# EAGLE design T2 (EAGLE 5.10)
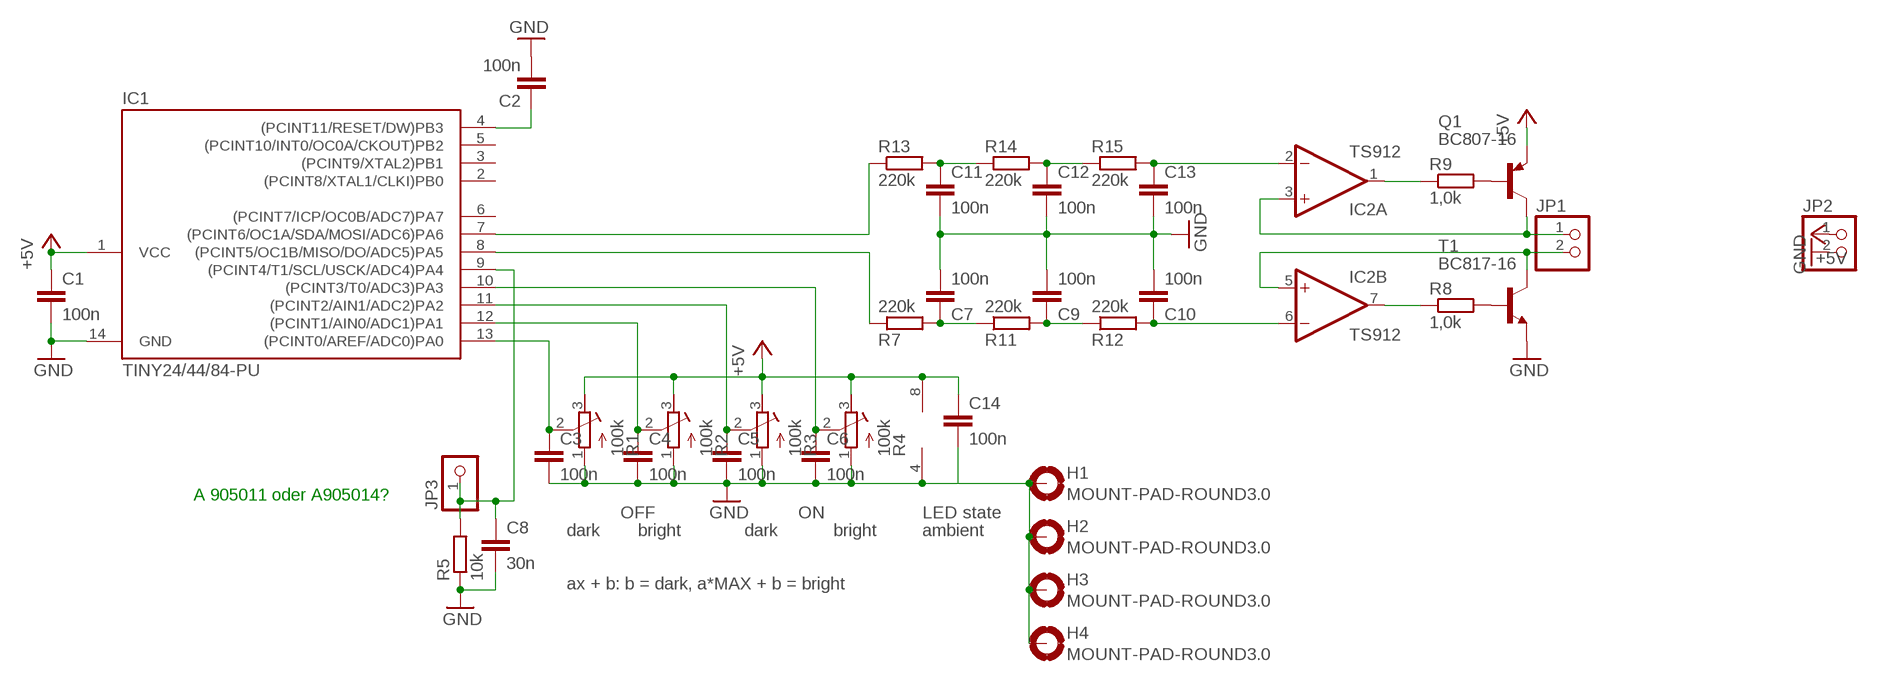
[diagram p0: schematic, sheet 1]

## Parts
C1  100n  C-EUC0805  [C0805]
C2  100n  C-EUC0805  [C0805]
C3  100n  C-EUC0805  [C0805]
C4  100n  C-EUC0805  [C0805]
C5  100n  C-EUC0805  [C0805]
C6  100n  C-EUC0805  [C0805]
C7  100n  C-EUC0805  [C0805]
C8  30n  C-EUC0805  [C0805]
C9  100n  C-EUC0805  [C0805]
C10  100n  C-EUC0805  [C0805]
C11  100n  C-EUC0805  [C0805]
C12  100n  C-EUC0805  [C0805]
C13  100n  C-EUC0805  [C0805]
C14  100n  C-EUC0805  [C0805]
H1  MOUNT-PAD-ROUND3.0  [3,0-PAD]
H2  MOUNT-PAD-ROUND3.0  [3,0-PAD]
H3  MOUNT-PAD-ROUND3.0  [3,0-PAD]
H4  MOUNT-PAD-ROUND3.0  [3,0-PAD]
IC1  TINY24/44/84-PU  [DIL14]
IC2  TS912  LM358N  [DIL08]
JP1  PINHD-1X2  [1X02]
JP2  PINHD-1X2  [1X02]
JP3  PINHD-1X1  [1X01]
Q1  BC807-16  BC807-16-PNP-SOT23-BEC  [SOT23-BEC]
R1  100k  R-TRIMM64W  [RTRIM64W]
R2  100k  R-TRIMM64W  [RTRIM64W]
R3  100k  R-TRIMM64W  [RTRIM64W]
R4  100k  R-TRIMM64W  [RTRIM64W]
R5  10k  R-EU_R0805  [R0805]
R7  220k  R-EU_R0805  [R0805]
R8  1,0k  R-EU_R0805  [R0805]
R9  1,0k  R-EU_R0805  [R0805]
R11  220k  R-EU_R0805  [R0805]
R12  220k  R-EU_R0805  [R0805]
R13  220k  R-EU_R0805  [R0805]
R14  220k  R-EU_R0805  [R0805]
R15  220k  R-EU_R0805  [R0805]
T1  BC817-16  BC817-16-NPN-SOT23-BEC  [SOT23-BEC]

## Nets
+5V: C1.1 C14.1 IC1.1(VCC) IC2.8(P:V+) JP2.1 Q1.E R1.3(A) R2.3(A) R3.3(A) R4.3(A)
GND: C1.2 C2.2 C3.2 C4.2 C5.2 C6.2 C7.2 C8.2 C9.2 C10.2 C11.2 C12.2 C13.2 C14.2 H1.B3,0(MOUNT) H2.B3,0(MOUNT) H3.B3,0(MOUNT) H4.B3,0(MOUNT) IC1.14(GND) IC2.4(P:V-) JP2.2 R1.1(E) R2.1(E) R3.1(E) R4.1(E) R5.1 T1.E
N$1: C2.1 IC1.4((PCINT11/RESET/DW)PB3)
N$3: IC2.7(B:OUT) R8.1
N$4: IC2.1(A:OUT) R9.1
N$5: IC1.8((PCINT5/OC1B/MISO/DO/ADC5)PA5) R7.1
N$6: IC1.7((PCINT6/OC1A/SDA/MOSI/ADC6)PA6) R13.1
N$7: C3.1 IC1.13((PCINT0/AREF/ADC0)PA0) R1.2(S)
N$8: C4.1 IC1.12((PCINT1/AIN0/ADC1)PA1) R2.2(S)
N$9: C5.1 IC1.11((PCINT2/AIN1/ADC2)PA2) R3.2(S)
N$10: C6.1 IC1.10((PCINT3/T0/ADC3)PA3) R4.2(S)
N$11: C8.1 IC1.9((PCINT4/T1/SCL/USCK/ADC4)PA4) JP3.1 R5.2
N$12: Q1.B R9.2
N$13: R8.2 T1.B
N$16: C7.1 R7.2 R11.1
N$17: C9.1 R11.2 R12.1
N$18: C10.1 IC2.6(B:-IN) R12.2
N$19: C11.1 R13.2 R14.1
N$20: C12.1 R14.2 R15.1
N$21: C13.1 IC2.2(A:-IN) R15.2
N$54: IC2.5(B:+IN) JP1.2 T1.C
N$55: IC2.3(A:+IN) JP1.1 Q1.C
Unconnected: IC1.2((PCINT8/XTAL1/CLKI)PB0) IC1.3((PCINT9/XTAL2)PB1) IC1.5((PCINT10/INT0/OC0A/CKOUT)PB2) IC1.6((PCINT7/ICP/OC0B/ADC7)PA7)

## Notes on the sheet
- A 905011 oder A905014?
- OFF | ON | LED state
- dark | bright | dark | bright | ambient
- ax + b: b = dark, a*MAX + b = bright

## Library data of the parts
C1-C14 = rcl:C-EU: CAPACITOR, European symbol
H1-H4 = holes:MOUNT-PAD-ROUND: MOUNTING PAD, round
IC1 = avr-6:TINY24/44/84
IC2 = linear:LM358: OP AMP also LM158; LM258; LM2904 Source: http://cache.national.com/ds/LM/LM158.pdf
JP1 JP2 = pinhead:PINHD-1X2: PIN HEADER
JP3 = pinhead:PINHD-1X1: PIN HEADER
Q1 = transistor:*-PNP-: PNP Transistror
R1-R4 = rcl:R-TRIMM: Trimm resistor
R5 R7-R9 R11-R15 = rcl:R-EU_: RESISTOR, European symbol
T1 = transistor:*-NPN-: NPN Transistror BF959 corrected 2008.03.06

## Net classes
1 Power: width 0.5 mm

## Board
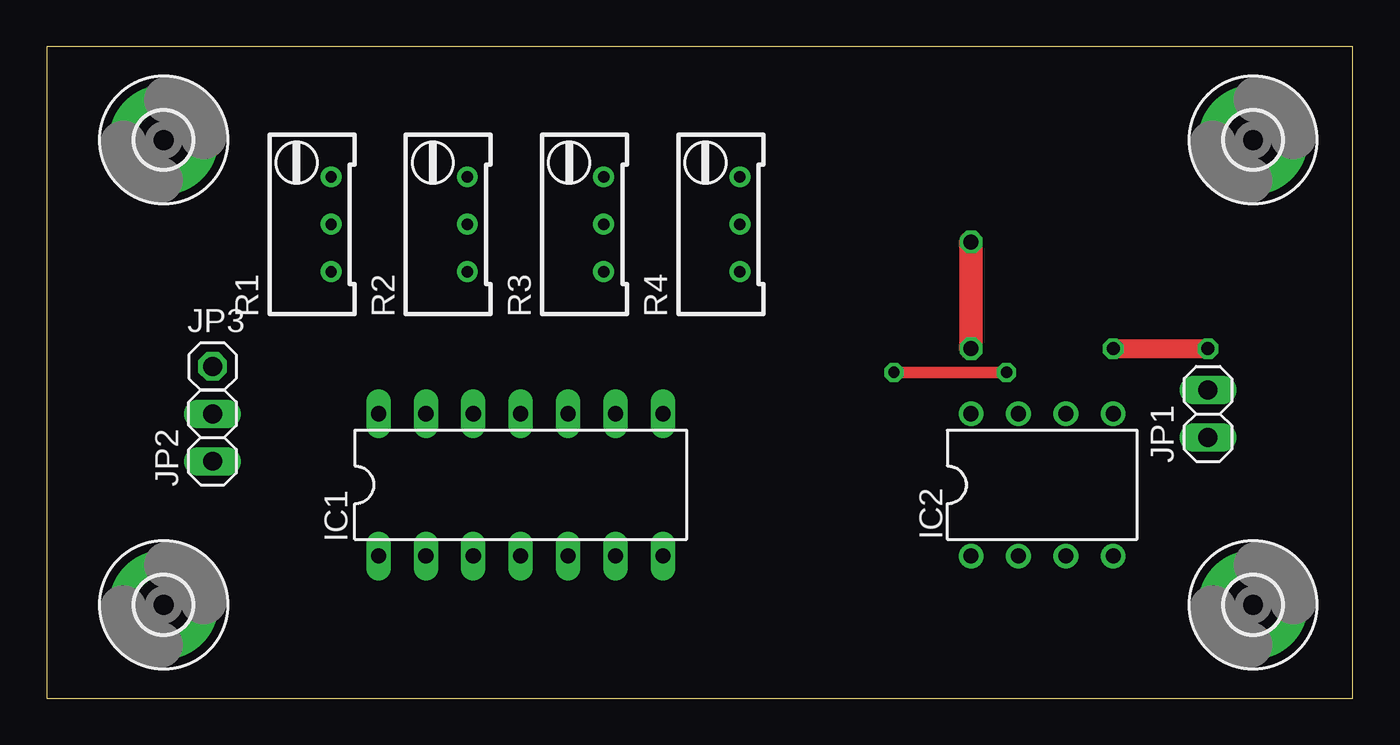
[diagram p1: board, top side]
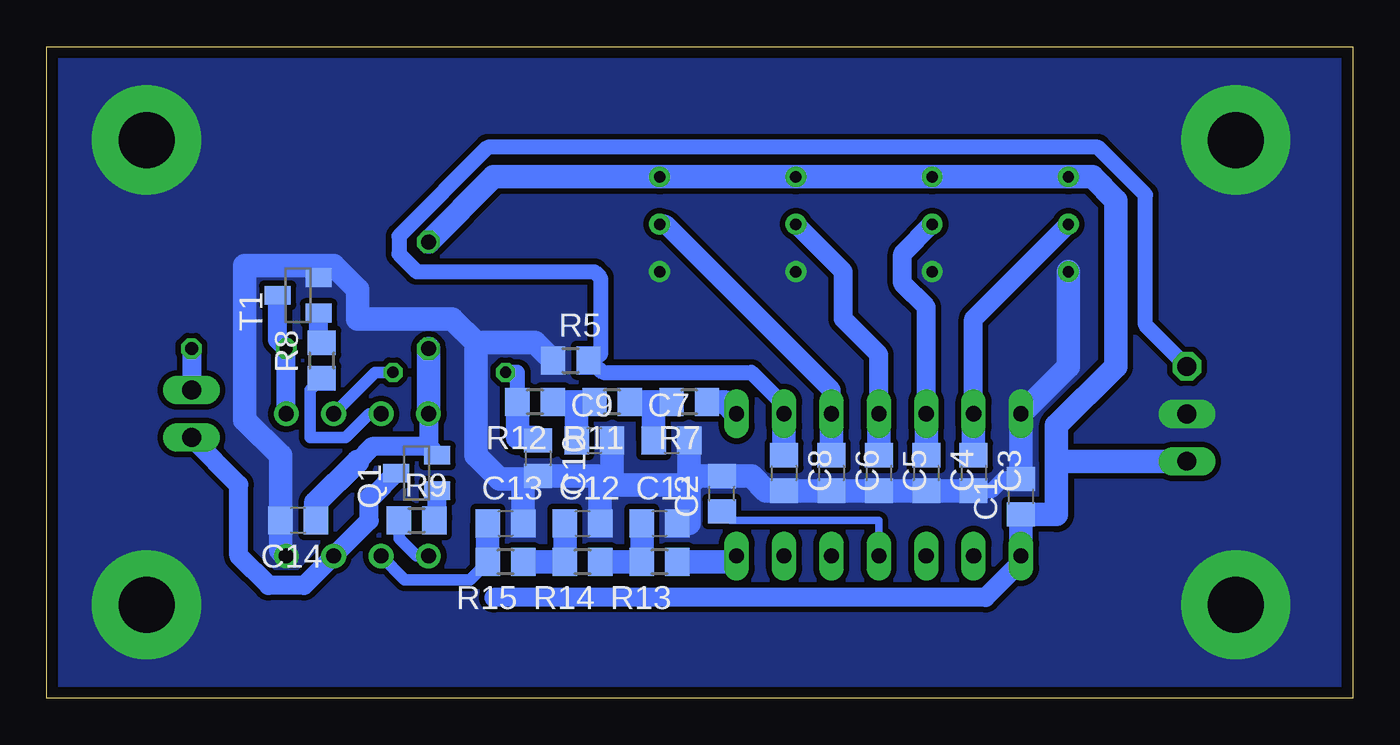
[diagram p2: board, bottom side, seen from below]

Size 69.99 x 34.92 mm. Coordinates in mm from the lower left corner, seen from the top.
Outline: 0,0 69.99,0 69.99,34.92 0,34.92 0,0
Copper layers (1*16): Top 0.035mm / dielectric 1.5mm / Bottom 0.035mm
Design rules "default *": minimum track width 10mil, minimum drill 24mil, track to track 0.3mm, track to pad 0.3mm, pad to pad 0.3mm, via to via 0.3mm, smd to smd 0.2mm, copper to edge 0.6mm, drill to drill 8mil, minimum pad ring 10mil, minimum via ring 8mil, stop-mask expansion 4mil, vias tented up to drill 0mil, thermal gap 10mil

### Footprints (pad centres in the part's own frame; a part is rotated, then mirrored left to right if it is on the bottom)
C0805 = smd 1.3 x 1.5: 1 -0.95,0; 2 0.95,0
3,0-PAD = drill 3 pad 5.842 round: B3,0 0,0
DIL14 = drill 0.813 long: 1 -7.62,-3.81; 2 -5.08,-3.81; 3 -2.54,-3.81; 4 0,-3.81; 5 2.54,-3.81; 6 5.08,-3.81; 7 7.62,-3.81; 8 7.62,3.81; 9 5.08,3.81; 10 2.54,3.81; 11 0,3.81; 12 -2.54,3.81; 13 -5.08,3.81; 14 -7.62,3.81
DIL08 = drill 0.813 pad 1.27 round: 1 -3.81,-3.81; 2 -1.27,-3.81; 3 1.27,-3.81; 4 3.81,-3.81; 5 3.81,3.81; 6 1.27,3.81; 7 -1.27,3.81; 8 -3.81,3.81
1X02 = drill 1.016 long: 1 -1.27,0; 2 1.27,0
1X01 = drill 1.016 octagon: 1 0,0
SOT23-BEC = smd 1 x 1.4: B -0.95,-1.1; C 0,1.1; E 0.95,-1.1
RTRIM64W = drill 0.61 round: 1 1.27,-2.54; 2 1.27,0; 3 1.27,2.54
R0805 = smd 1.3 x 1.5: 1 -0.95,0; 2 0.95,0

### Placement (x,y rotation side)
C1  17.78,10.79 90 bottom
C2  33.81,10.95 90 bottom
C3  20.32,12.06 270 bottom
C4  22.86,12.06 270 bottom
C5  25.4,12.06 270 bottom
C6  27.94,12.06 270 bottom
C7  36.51,13.81 0 bottom
C8  30.48,12.06 270 bottom
C9  40.64,13.81 0 bottom
C10  43.66,12.86 270 bottom
C11  37.15,9.37 0 bottom
C12  41.27,9.37 0 bottom
C13  45.4,9.37 0 bottom
C14  56.52,9.53 180 bottom
H1  64.64,5 0 top
H2  64.64,29.92 0 top
H3  6.26,5 0 top
H4  6.26,29.92 0 top
IC1  25.4,11.43 0 top
IC2  53.34,11.43 0 top
JP1  62.23,15.24 90 top
JP2  8.89,13.97 90 top
JP3  8.89,17.78 0 top
Q1  50.16,12.06 90 bottom
R1  13.97,25.4 0 top
R2  21.27,25.4 0 top
R3  28.57,25.4 0 top
R4  35.88,25.4 0 top
R5  41.91,18.1 0 bottom
R7  35.56,15.88 180 bottom
R8  55.24,18.1 90 bottom
R9  50.16,9.53 0 bottom
R11  39.69,15.88 180 bottom
R12  43.81,15.88 180 bottom
R13  37.15,7.3 180 bottom
R14  41.27,7.3 180 bottom
R15  45.4,7.3 180 bottom
T1  56.52,21.59 90 bottom

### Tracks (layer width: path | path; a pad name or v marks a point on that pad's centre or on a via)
+5V  (via drill 0.8)
  Top 1.27: v49.53,24.45 v49.53,18.73
  Bottom 1.016: IC2.8 49.53,13.48 | 53.34,12.7 52.56,13.48 49.53,13.48 | 17.78,7.3 19.68,5.4 46.04,5.4 | 49.53,13.48 Q1.E
  Bottom 1.27: 53.34,12.7 55.56,10.47 C14.1 | v49.53,18.73 IC2.8 | 15.88,12.7 15.88,9.85 C1.1 IC1.1 17.78,7.3 | 15.88,12.7 15.88,14.61 12.7,17.78 12.7,26.67 13.97,27.94 R1.3 R2.3 R3.3 R4.3 46.04,27.94 v49.53,24.45 | JP2.1 15.88,12.7
GND
  Bottom 0.813: C3.2 19.36,11.12 18.73,11.74 C1.2
  Bottom 1.016: T1.E 55.88,23 55.88,23.18
  Bottom 1.27: C3.2 C4.2 C5.2 C6.2 C8.2 31.43,11.12 32.22,11.9 C2.2 35.09,11.9 35.56,11.43 | C1.2 IC1.14 15.24,17.78 R1.1 | IC2.4 57.47,7.93 C14.2 57.47,13.02 59.37,14.92 59.37,23.18 55.88,23.18 54.61,23.18 53.34,21.91 53.34,20.32 48.26,20.32 46.99,19.05 | R5.1 43.81,19.05 46.99,19.05 | C11.2 35.56,9.37 35.56,11.43 | 35.56,11.43 C7.2 | 44.45,11.43 44.45,11.75 45.72,11.75 46.99,13.02 46.99,19.05 | 44.45,11.43 C13.2 | 40.33,11.43 C12.2 | 40.33,11.43 40.33,11.75 40.48,11.91 C10.2 43.97,11.91 44.45,11.43 | 35.56,11.43 39.69,11.43 | 39.69,11.43 C9.2 | 39.69,11.43 40.33,11.43
  pour Bottom (isolate 0.3, rank 5, no thermals): 0,34.92 0,0 69.99,0 69.99,34.92
N$1
  Bottom 0.406: IC1.4 25.4,9.53 33.34,9.53 C2.1
N$3
  Bottom 0.61: IC2.7 52.7,15.24 53.98,13.97 55.88,13.97 55.88,16.51 R8.1
N$4
  Bottom 0.61: R9.1 51.12,8.57 50.16,7.62 IC2.1
N$5
  Bottom 1.27: IC1.8 33.66,15.88 R7.1
N$6
  Bottom 1.27: R13.1 33.34,7.3 IC1.7
N$7
  Bottom 1.016: R1.2 20.32,20.32 IC1.13
  Bottom 1.27: C3.1 IC1.13
N$8
  Bottom 1.016: R2.2 24.13,23.81 24.13,22.23 22.86,20.95 IC1.12
  Bottom 1.27: C4.1 IC1.12
N$9
  Bottom 1.016: IC1.11 25.4,18.41 27.3,20.32 27.3,22.86 R3.2
  Bottom 1.27: C5.1 IC1.11
N$10
  Bottom 1.016: IC1.10 27.94,16.51 36.83,25.4 R4.2
  Bottom 1.27: C6.1 IC1.10
N$11
  Bottom 0.813: IC1.9 30.64,15.88 32.23,17.46 40.17,17.46 R5.2 40.32,18.42 40.32,22.54 40.64,22.86 50.16,22.86 51.12,23.81 51.12,24.77 46.35,29.53 13.65,29.53 11.11,26.99 11.11,20 JP3.1
  Bottom 1.27: IC1.9 C8.1
N$12
  Bottom 1.016: Q1.B 49.06,9.68 R9.2
N$13
  Bottom 1.016: T1.B 55.41,19.22 R8.2
N$16
  Bottom 1.27: R11.1 R7.2 37.46,15.88 C7.1
N$17
  Bottom 1.27: 41.59,15.88 R11.2 | C9.1 41.59,15.88 | 41.59,15.88 R12.1
N$18  (via drill 0.61)
  Top 0.61: v45.4,17.46 v51.44,17.46
  Bottom 0.61: v51.44,17.46 52.39,17.46 IC2.6
  Bottom 0.813: v45.4,17.46 44.77,17.46 R12.2
  Bottom 1.27: C10.1 43.81,13.97 44.77,13.97 R12.2
N$19
  Bottom 1.27: R14.1 R13.2 C11.1
N$20
  Bottom 1.27: R15.1 R14.2 C12.1
N$21
  Bottom 0.61: IC2.2 50.8,6.35 47.3,6.35 R15.2
  Bottom 1.27: R15.2 C13.1
N$54  (via drill 0.7)
  Top 1.016: v57.15,18.73 v62.23,18.73
  Bottom 1.016: IC2.5 v57.15,18.73 57.62,19.2 T1.C | v62.23,18.73 JP1.2 | v62.23,18.73
N$55
  Bottom 1.016: Q1.C 52.53,10.79 52.7,10.79 52.7,9.53 IC2.3 56.2,6.03 58.1,6.03 59.69,7.62 59.69,11.43 JP1.1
